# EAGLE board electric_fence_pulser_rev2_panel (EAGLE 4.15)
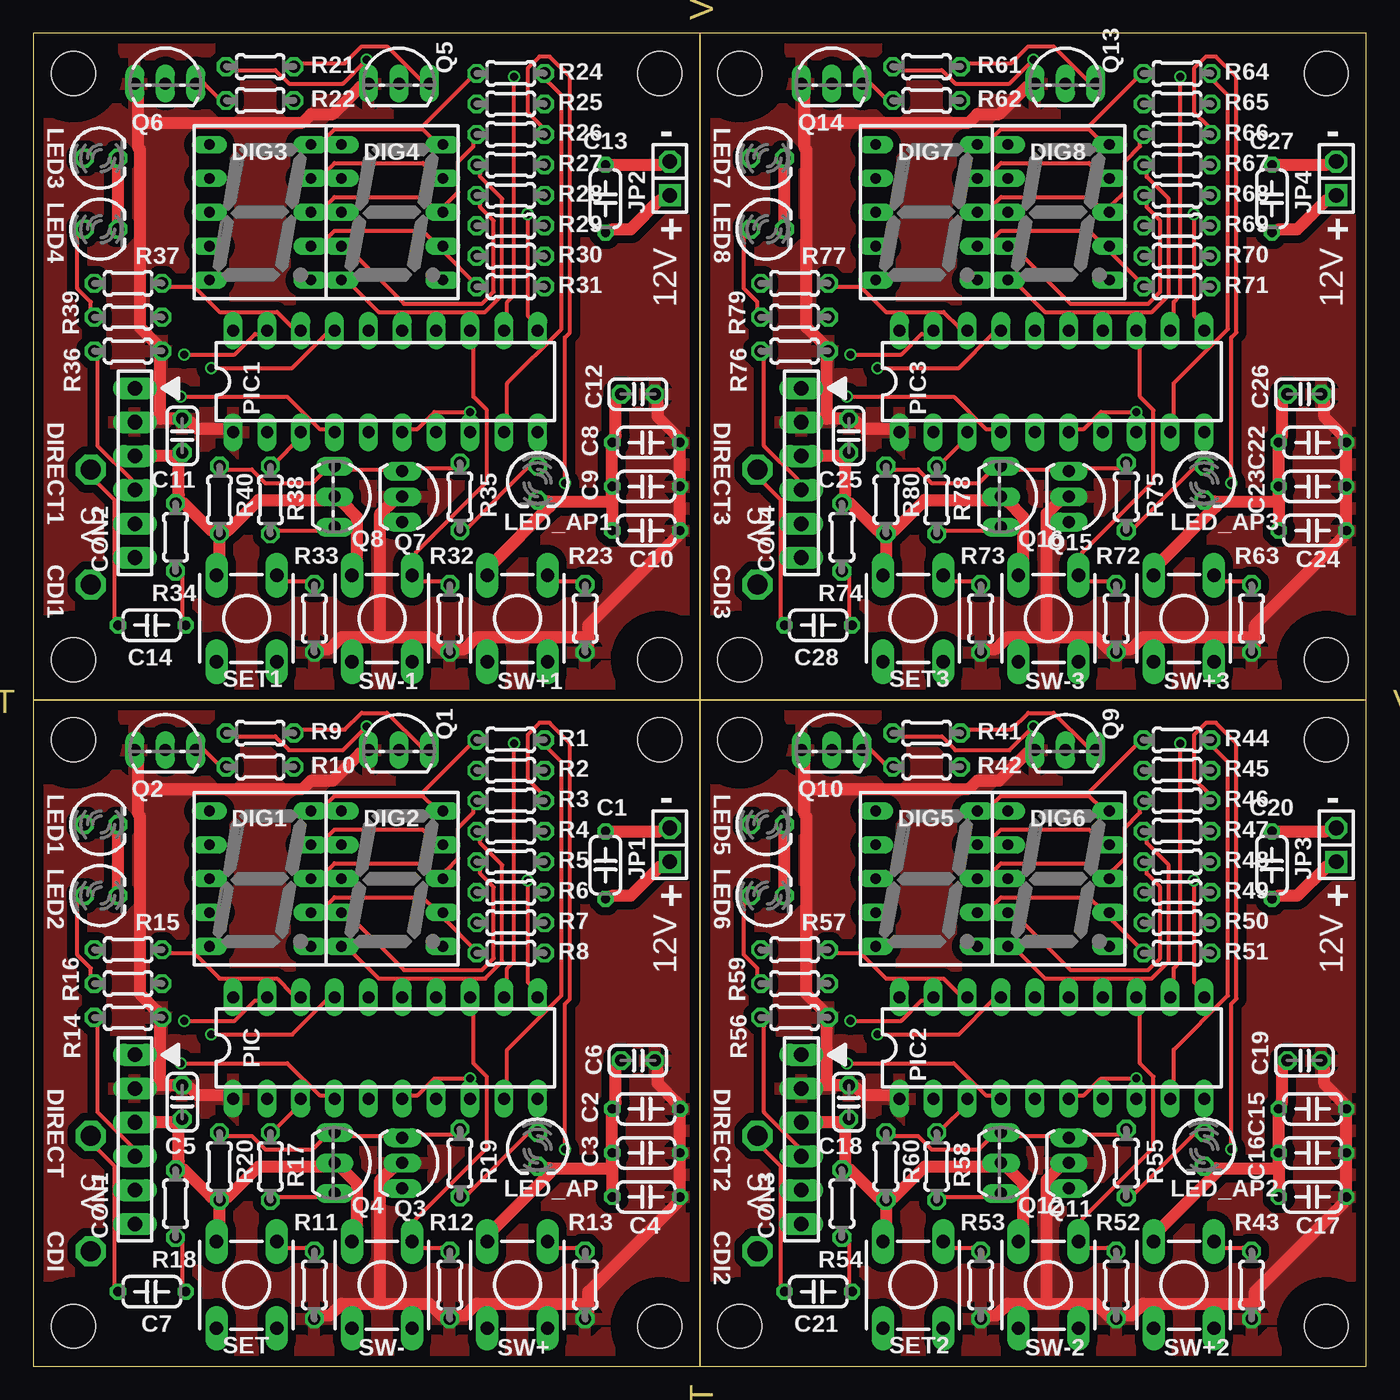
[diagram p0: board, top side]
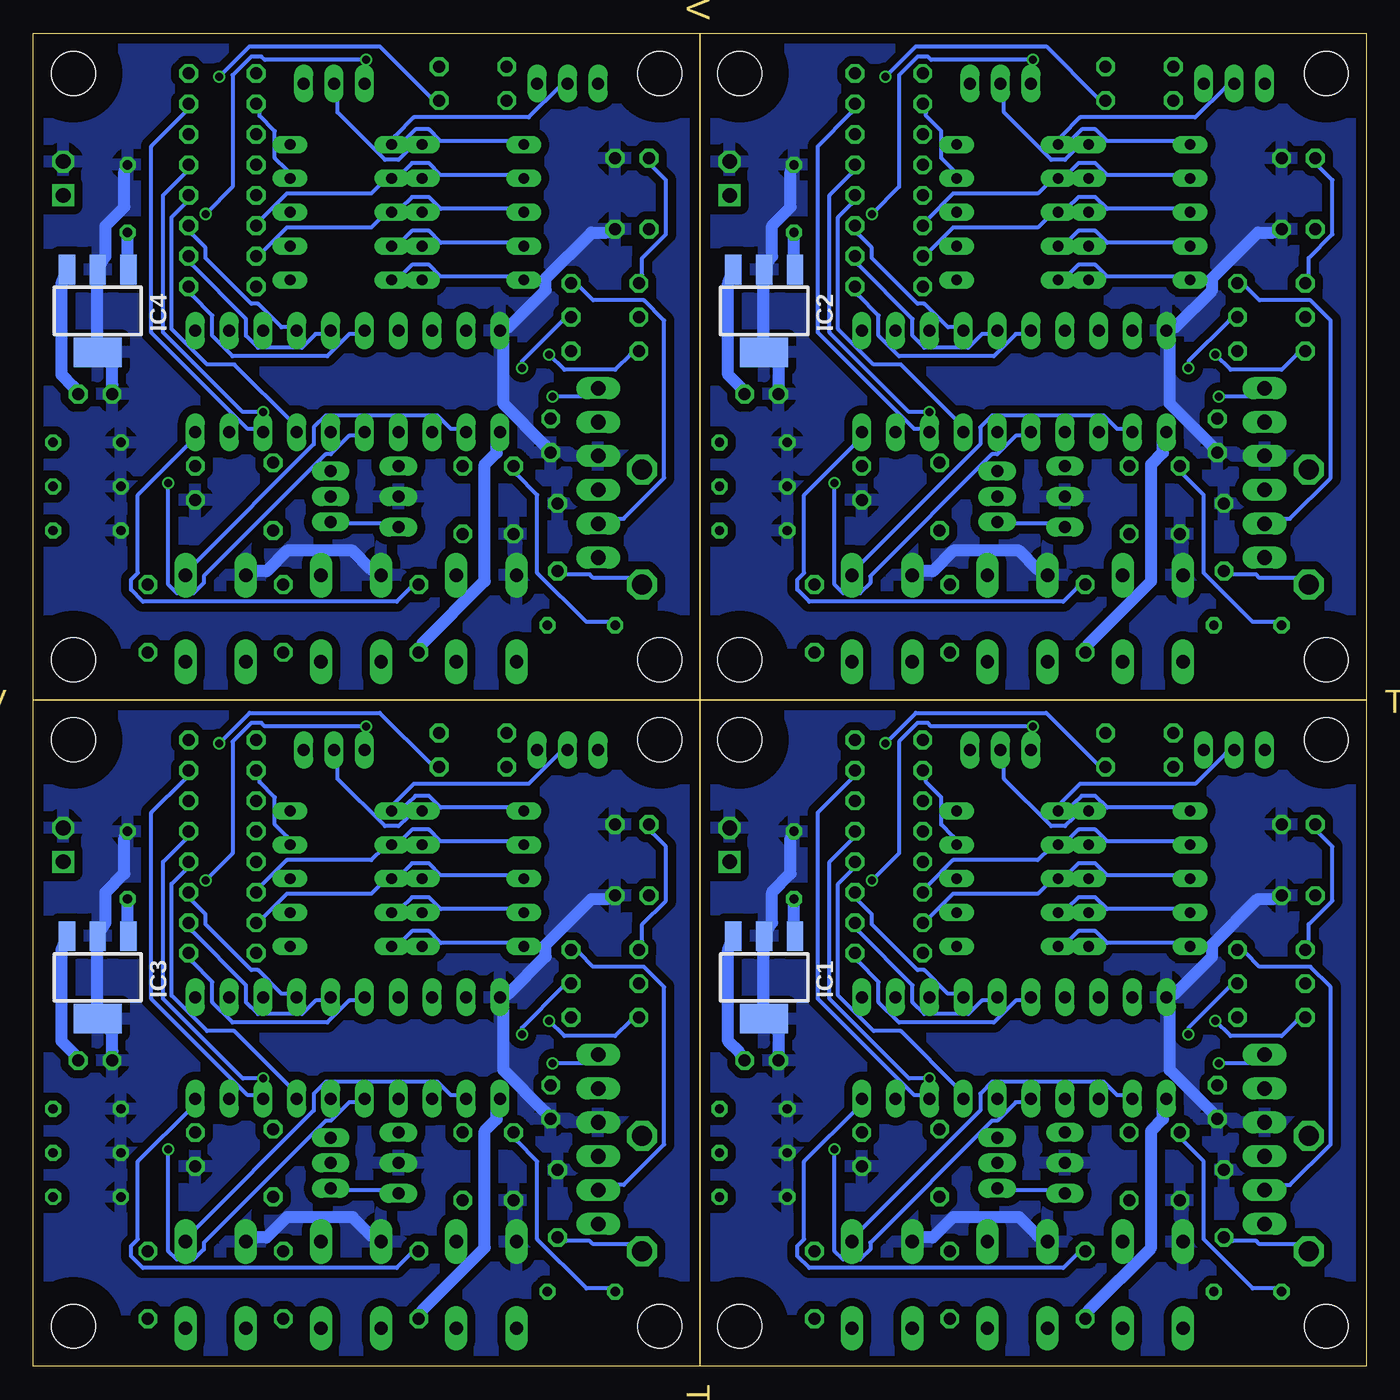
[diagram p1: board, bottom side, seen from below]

Size 100 x 100 mm. Coordinates in mm from the lower left corner, seen from the top.
Outline: 50,0 0,0 0,50
Outline: 50,0 50,50
Outline: 50,50 0,50
Outline: 0,50 50,50
Outline: 50,50 50,100
Outline: 50,100 0,100 0,50
Outline: 50,0 100,0 100,50
Outline: 100,50 50,50
Outline: 50,50 50,0
Outline: 50,50 100,50
Outline: 100,50 100,100 50,100
Outline: 50,100 50,50
Copper layers (1*16): Top 0.035mm / dielectric 1.5mm / Bottom 0.035mm
Design rules "FUSION_IIZUKA_STANDARD": minimum track width 6mil, minimum drill 0.6mm, track to track 8mil, track to pad 8mil, pad to pad 8mil, via to via 8mil, smd to smd 0mil, copper to edge 30mil, drill to drill 10mil, minimum pad ring 10mil, minimum via ring 6mil, stop-mask expansion 2mil, vias tented up to drill 100mil, thermal gap 24mil
Net classes: 0 default: width 0.305 mm, drill 0.305 mm; 1 POWER: width 0.889 mm, drill 0.457 mm
vRestrict: 3264 lines

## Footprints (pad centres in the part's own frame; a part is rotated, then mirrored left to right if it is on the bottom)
C050-024X044_OLMX = drill 0.7 octagon: 1 -2.54,0; 2 2.54,0
C025-024X044_OLMX = drill 0.9 octagon: 1 -1.27,0; 2 1.27,0
PAD_1.5 = drill 1.5 pad 2.184 octagon: P$1 0,0
PIC_ICSP = drill 1.1 long: MCLR -6.35,0; NC 6.35,0; PGC 3.81,0; PGD 1.27,0; VDD -3.81,0; VSS -1.27,0
HDSP-E_OLMX = drill 0.8 long: 1 -3.81,5.08; 2 -3.81,2.54; 3 -3.81,0; 4 -3.81,-2.54; 5 -3.81,-5.08; 6 3.81,-5.08; 7 3.81,-2.54; 8 3.81,0; 9 3.81,2.54; 10 3.81,5.08
3.0-HOLL-ONLY-RESTRICT = hole 3.3: 0,0
SOT223_OLMX = smd 1.219 x 2.235: 1 -2.311,-3.099; 2 0,-3.099; 3 2.311,-3.099 | smd 3.6 x 2.2: 4 0,3.099
1X02_OLMX = drill 1.1 square: 1 -1.27,0 | drill 1.1 octagon: 2 1.27,0
LED3MM_OLMX = drill 0.9 octagon: A -1.27,0; K 1.27,0
DIL20_OLMX = drill 0.9 long: 1 -11.43,-3.81; 2 -8.89,-3.81; 3 -6.35,-3.81; 4 -3.81,-3.81; 5 -1.27,-3.81; 6 1.27,-3.81; 7 3.81,-3.81; 8 6.35,-3.81; 9 8.89,-3.81; 10 11.43,-3.81; 11 11.43,3.81; 12 8.89,3.81; 13 6.35,3.81; 14 3.81,3.81; 15 1.27,3.81; 16 -1.27,3.81; 17 -3.81,3.81; 18 -6.35,3.81; 19 -8.89,3.81; 20 -11.43,3.81
TO-92-BCE?NALLOW = drill 0.9 long: B 2.286,0; C 0,0; E -2.286,0
TO92-BCE_OLMX_NALLOW = drill 0.9 long: B 1.905,0; C 0,0; E -1.905,0
0204/5_OLMX = drill 0.9 octagon: 1 -2.54,0; 2 2.54,0
TACT_SW = drill 1 pad 1.676 long: P$1_1 -2.261,3.251; P$1_2 2.261,3.251; P$2_1 -2.261,-3.251; P$2_2 2.261,-3.251

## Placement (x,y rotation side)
C1  10uF  [C050-024X044_OLMX]  42.93,37.59 270 top
C2  10uF  [C050-024X044_OLMX]  45.97,19.3 0 top
C3  10uF  [C050-024X044_OLMX]  45.97,16 0 top
C4  10uF  [C050-024X044_OLMX]  45.97,12.7 0 top
C5  0.1uF  [C025-024X044_OLMX]  11.18,19.81 90 top
C6  0.1uF  [C025-024X044_OLMX]  45.36,22.93 0 top
C7  0.1uF  [C050-024X044_OLMX]  8.89,5.59 180 top
C8  10uF  [C050-024X044_OLMX]  45.97,69.3 0 top
C9  10uF  [C050-024X044_OLMX]  45.97,66 0 top
C10  10uF  [C050-024X044_OLMX]  45.97,62.7 0 top
C11  0.1uF  [C025-024X044_OLMX]  11.18,69.81 90 top
C12  0.1uF  [C025-024X044_OLMX]  45.36,72.93 0 top
C13  10uF  [C050-024X044_OLMX]  42.93,87.59 270 top
C14  0.1uF  [C050-024X044_OLMX]  8.89,55.59 180 top
C15  10uF  [C050-024X044_OLMX]  95.97,19.3 0 top
C16  10uF  [C050-024X044_OLMX]  95.97,16 0 top
C17  10uF  [C050-024X044_OLMX]  95.97,12.7 0 top
C18  0.1uF  [C025-024X044_OLMX]  61.18,19.81 90 top
C19  0.1uF  [C025-024X044_OLMX]  95.36,22.93 0 top
C20  10uF  [C050-024X044_OLMX]  92.93,37.59 270 top
C21  0.1uF  [C050-024X044_OLMX]  58.89,5.59 180 top
C22  10uF  [C050-024X044_OLMX]  95.97,69.3 0 top
C23  10uF  [C050-024X044_OLMX]  95.97,66 0 top
C24  10uF  [C050-024X044_OLMX]  95.97,62.7 0 top
C25  0.1uF  [C025-024X044_OLMX]  61.18,69.81 90 top
C26  0.1uF  [C025-024X044_OLMX]  95.36,72.93 0 top
C27  10uF  [C050-024X044_OLMX]  92.93,87.59 270 top
C28  0.1uF  [C050-024X044_OLMX]  58.89,55.59 180 top
CDI  PAD1.5  [PAD_1.5]  4.32,8.64 270 top
CDI1  PAD1.5  [PAD_1.5]  4.32,58.64 270 top
CDI2  PAD1.5  [PAD_1.5]  54.32,8.64 270 top
CDI3  PAD1.5  [PAD_1.5]  54.32,58.64 270 top
CON1  ICSP  [PIC_ICSP]  7.62,17.02 270 top
CON2  ICSP  [PIC_ICSP]  7.62,67.02 270 top
CON3  ICSP  [PIC_ICSP]  57.62,17.02 270 top
CON4  ICSP  [PIC_ICSP]  57.62,67.02 270 top
DIG1  GL9A040G  [HDSP-E_OLMX]  17.02,36.58 0 top
DIG2  GL9A040G  [HDSP-E_OLMX]  26.92,36.58 0 top
DIG3  GL9A040G  [HDSP-E_OLMX]  17.02,86.58 0 top
DIG4  GL9A040G  [HDSP-E_OLMX]  26.92,86.58 0 top
DIG5  GL9A040G  [HDSP-E_OLMX]  67.02,36.58 0 top
DIG6  GL9A040G  [HDSP-E_OLMX]  76.92,36.58 0 top
DIG7  GL9A040G  [HDSP-E_OLMX]  67.02,86.58 0 top
DIG8  GL9A040G  [HDSP-E_OLMX]  76.92,86.58 0 top
DIRECT  PAD1.5  [PAD_1.5]  4.32,17.27 270 top
DIRECT1  PAD1.5  [PAD_1.5]  4.32,67.27 270 top
DIRECT2  PAD1.5  [PAD_1.5]  54.32,17.27 270 top
DIRECT3  PAD1.5  [PAD_1.5]  54.32,67.27 270 top
H1  MOUNT-HOLE  [3.0-HOLL-ONLY-RESTRICT]  47,47 0 top
H2  MOUNT-HOLE  [3.0-HOLL-ONLY-RESTRICT]  47,3 0 top
H3  MOUNT-HOLE  [3.0-HOLL-ONLY-RESTRICT]  3,3 0 top
H4  MOUNT-HOLE  [3.0-HOLL-ONLY-RESTRICT]  3,47 0 top
H5  MOUNT-HOLE  [3.0-HOLL-ONLY-RESTRICT]  47,97 0 top
H6  MOUNT-HOLE  [3.0-HOLL-ONLY-RESTRICT]  47,53 0 top
H7  MOUNT-HOLE  [3.0-HOLL-ONLY-RESTRICT]  3,53 0 top
H8  MOUNT-HOLE  [3.0-HOLL-ONLY-RESTRICT]  3,97 0 top
H9  MOUNT-HOLE  [3.0-HOLL-ONLY-RESTRICT]  97,47 0 top
H10  MOUNT-HOLE  [3.0-HOLL-ONLY-RESTRICT]  97,3 0 top
H11  MOUNT-HOLE  [3.0-HOLL-ONLY-RESTRICT]  53,3 0 top
H12  MOUNT-HOLE  [3.0-HOLL-ONLY-RESTRICT]  53,47 0 top
H13  MOUNT-HOLE  [3.0-HOLL-ONLY-RESTRICT]  97,97 0 top
H14  MOUNT-HOLE  [3.0-HOLL-ONLY-RESTRICT]  97,53 0 top
H15  MOUNT-HOLE  [3.0-HOLL-ONLY-RESTRICT]  53,53 0 top
H16  MOUNT-HOLE  [3.0-HOLL-ONLY-RESTRICT]  53,97 0 top
IC1  LM2940IMP  [SOT223_OLMX]  45.17,29.17 180 bottom
IC2  LM2940IMP  [SOT223_OLMX]  45.17,79.17 180 bottom
IC3  LM2940IMP  [SOT223_OLMX]  95.17,29.17 180 bottom
IC4  LM2940IMP  [SOT223_OLMX]  95.17,79.17 180 bottom
JP1  [1X02_OLMX]  47.75,39.12 90 top
JP2  [1X02_OLMX]  47.75,89.12 90 top
JP3  [1X02_OLMX]  97.75,39.12 90 top
JP4  [1X02_OLMX]  97.75,89.12 90 top
LED1  [LED3MM_OLMX]  5.08,40.64 0 top
LED2  [LED3MM_OLMX]  5.08,35.31 0 top
LED3  [LED3MM_OLMX]  5.08,90.64 0 top
LED4  [LED3MM_OLMX]  5.08,85.31 0 top
LED5  [LED3MM_OLMX]  55.08,40.64 0 top
LED6  [LED3MM_OLMX]  55.08,35.31 0 top
LED7  [LED3MM_OLMX]  55.08,90.64 0 top
LED8  [LED3MM_OLMX]  55.08,85.31 0 top
LED_AP  [LED3MM_OLMX]  37.85,16.26 270 top
LED_AP1  [LED3MM_OLMX]  37.85,66.26 270 top
LED_AP2  [LED3MM_OLMX]  87.85,16.26 270 top
LED_AP3  [LED3MM_OLMX]  87.85,66.26 270 top
PIC  PIC16F  [DIL20_OLMX]  26.42,23.88 0 top
PIC1  PIC16F  [DIL20_OLMX]  26.42,73.88 0 top
PIC2  PIC16F  [DIL20_OLMX]  76.42,23.88 0 top
PIC3  PIC16F  [DIL20_OLMX]  76.42,73.88 0 top
Q1  2SA1015Y  [TO-92-BCE?NALLOW]  27.43,46.23 0 top
Q2  2SA1015Y  [TO-92-BCE?NALLOW]  9.91,46.23 0 top
Q3  2SC1815Y  [TO92-BCE_OLMX_NALLOW]  27.69,15.24 270 top
Q4  2SA1015Y  [TO-92-BCE?NALLOW]  22.61,15.24 270 top
Q5  2SA1015Y  [TO-92-BCE?NALLOW]  27.43,96.23 0 top
Q6  2SA1015Y  [TO-92-BCE?NALLOW]  9.91,96.23 0 top
Q7  2SC1815Y  [TO92-BCE_OLMX_NALLOW]  27.69,65.24 270 top
Q8  2SA1015Y  [TO-92-BCE?NALLOW]  22.61,65.24 270 top
Q9  2SA1015Y  [TO-92-BCE?NALLOW]  77.43,46.23 0 top
Q10  2SA1015Y  [TO-92-BCE?NALLOW]  59.91,46.23 0 top
Q11  2SC1815Y  [TO92-BCE_OLMX_NALLOW]  77.69,15.24 270 top
Q12  2SA1015Y  [TO-92-BCE?NALLOW]  72.61,15.24 270 top
Q13  2SA1015Y  [TO-92-BCE?NALLOW]  77.43,96.23 0 top
Q14  2SA1015Y  [TO-92-BCE?NALLOW]  59.91,96.23 0 top
Q15  2SC1815Y  [TO92-BCE_OLMX_NALLOW]  77.69,65.24 270 top
Q16  2SA1015Y  [TO-92-BCE?NALLOW]  72.61,65.24 270 top
R1  220  [0204/5_OLMX]  35.81,46.99 0 top
R2  220  [0204/5_OLMX]  35.81,44.7 0 top
R3  220  [0204/5_OLMX]  35.81,42.42 0 top
R4  220  [0204/5_OLMX]  35.81,40.13 0 top
R5  220  [0204/5_OLMX]  35.81,37.85 0 top
R6  220  [0204/5_OLMX]  35.81,35.56 0 top
R7  220  [0204/5_OLMX]  35.81,33.27 0 top
R8  220  [0204/5_OLMX]  35.81,30.99 0 top
R9  4.7k  [0204/5_OLMX]  17.02,47.5 180 top
R10  4.7k  [0204/5_OLMX]  17.02,44.96 0 top
R11  10k  [0204/5_OLMX]  21.08,6.1 270 top
R12  10k  [0204/5_OLMX]  31.24,6.1 270 top
R13  10k  [0204/5_OLMX]  41.4,6.1 270 top
R14  10k  [0204/5_OLMX]  7.11,26.16 180 top
R15  1k  [0204/5_OLMX]  7.11,31.24 180 top
R16  1k  [0204/5_OLMX]  7.11,28.7 180 top
R17  1k  [0204/5_OLMX]  17.78,14.99 270 top
R18  10k  [0204/5_OLMX]  10.67,12.19 90 top
R19  1k  [0204/5_OLMX]  32,15.24 270 top
R20  1k  [0204/5_OLMX]  13.97,14.99 270 top
R21  4.7k  [0204/5_OLMX]  17.02,97.5 180 top
R22  4.7k  [0204/5_OLMX]  17.02,94.96 0 top
R23  10k  [0204/5_OLMX]  41.4,56.1 270 top
R24  220  [0204/5_OLMX]  35.81,96.99 0 top
R25  220  [0204/5_OLMX]  35.81,94.7 0 top
R26  220  [0204/5_OLMX]  35.81,92.42 0 top
R27  220  [0204/5_OLMX]  35.81,90.13 0 top
R28  220  [0204/5_OLMX]  35.81,87.85 0 top
R29  220  [0204/5_OLMX]  35.81,85.56 0 top
R30  220  [0204/5_OLMX]  35.81,83.27 0 top
R31  220  [0204/5_OLMX]  35.81,80.99 0 top
R32  10k  [0204/5_OLMX]  31.24,56.1 270 top
R33  10k  [0204/5_OLMX]  21.08,56.1 270 top
R34  10k  [0204/5_OLMX]  10.67,62.19 90 top
R35  1k  [0204/5_OLMX]  32,65.24 270 top
R36  10k  [0204/5_OLMX]  7.11,76.16 180 top
R37  1k  [0204/5_OLMX]  7.11,81.24 180 top
R38  1k  [0204/5_OLMX]  17.78,64.99 270 top
R39  1k  [0204/5_OLMX]  7.11,78.7 180 top
R40  1k  [0204/5_OLMX]  13.97,64.99 270 top
R41  4.7k  [0204/5_OLMX]  67.02,47.5 180 top
R42  4.7k  [0204/5_OLMX]  67.02,44.96 0 top
R43  10k  [0204/5_OLMX]  91.4,6.1 270 top
R44  220  [0204/5_OLMX]  85.81,46.99 0 top
R45  220  [0204/5_OLMX]  85.81,44.7 0 top
R46  220  [0204/5_OLMX]  85.81,42.42 0 top
R47  220  [0204/5_OLMX]  85.81,40.13 0 top
R48  220  [0204/5_OLMX]  85.81,37.85 0 top
R49  220  [0204/5_OLMX]  85.81,35.56 0 top
R50  220  [0204/5_OLMX]  85.81,33.27 0 top
R51  220  [0204/5_OLMX]  85.81,30.99 0 top
R52  10k  [0204/5_OLMX]  81.24,6.1 270 top
R53  10k  [0204/5_OLMX]  71.08,6.1 270 top
R54  10k  [0204/5_OLMX]  60.67,12.19 90 top
R55  1k  [0204/5_OLMX]  82,15.24 270 top
R56  10k  [0204/5_OLMX]  57.11,26.16 180 top
R57  1k  [0204/5_OLMX]  57.11,31.24 180 top
R58  1k  [0204/5_OLMX]  67.78,14.99 270 top
R59  1k  [0204/5_OLMX]  57.11,28.7 180 top
R60  1k  [0204/5_OLMX]  63.97,14.99 270 top
R61  4.7k  [0204/5_OLMX]  67.02,97.5 180 top
R62  4.7k  [0204/5_OLMX]  67.02,94.96 0 top
R63  10k  [0204/5_OLMX]  91.4,56.1 270 top
R64  220  [0204/5_OLMX]  85.81,96.99 0 top
R65  220  [0204/5_OLMX]  85.81,94.7 0 top
R66  220  [0204/5_OLMX]  85.81,92.42 0 top
R67  220  [0204/5_OLMX]  85.81,90.13 0 top
R68  220  [0204/5_OLMX]  85.81,87.85 0 top
R69  220  [0204/5_OLMX]  85.81,85.56 0 top
R70  220  [0204/5_OLMX]  85.81,83.27 0 top
R71  220  [0204/5_OLMX]  85.81,80.99 0 top
R72  10k  [0204/5_OLMX]  81.24,56.1 270 top
R73  10k  [0204/5_OLMX]  71.08,56.1 270 top
R74  10k  [0204/5_OLMX]  60.67,62.19 90 top
R75  1k  [0204/5_OLMX]  82,65.24 270 top
R76  10k  [0204/5_OLMX]  57.11,76.16 180 top
R77  1k  [0204/5_OLMX]  57.11,81.24 180 top
R78  1k  [0204/5_OLMX]  67.78,64.99 270 top
R79  1k  [0204/5_OLMX]  57.11,78.7 180 top
R80  1k  [0204/5_OLMX]  63.97,64.99 270 top
SET  PUSH_SWTACT  [TACT_SW]  16,6.1 0 top
SET1  PUSH_SWTACT  [TACT_SW]  16,56.1 0 top
SET2  PUSH_SWTACT  [TACT_SW]  66,6.1 0 top
SET3  PUSH_SWTACT  [TACT_SW]  66,56.1 0 top
SW+  PUSH_SWTACT  [TACT_SW]  36.32,6.1 0 top
SW+1  PUSH_SWTACT  [TACT_SW]  36.32,56.1 0 top
SW+2  PUSH_SWTACT  [TACT_SW]  86.32,6.1 0 top
SW+3  PUSH_SWTACT  [TACT_SW]  86.32,56.1 0 top
SW-  PUSH_SWTACT  [TACT_SW]  26.16,6.1 0 top
SW-1  PUSH_SWTACT  [TACT_SW]  26.16,56.1 0 top
SW-2  PUSH_SWTACT  [TACT_SW]  76.16,6.1 0 top
SW-3  PUSH_SWTACT  [TACT_SW]  76.16,56.1 0 top

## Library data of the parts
C1-C28 R1-R80 = rcl
CDI CDI1-CDI3 CON1-CON4 DIRECT DIRECT1-DIRECT3 SET SET1-SET3 SW+ SW+1-SW+3 SW- SW-1-SW-3 = 001mylib
DIG1-DIG8 = display-hp
H1-H16 = holes
IC1-IC4 = linear
JP1-JP4 = pinhead
LED1-LED8 LED_AP LED_AP1-LED_AP3 = led
PIC PIC1-PIC3 = microchip-5
Q1 Q2 Q4-Q6 Q8-Q10 Q12-Q14 Q16 = transistor-pnp
Q3 Q7 Q11 Q15 = transistor

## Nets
+12V [POWER]: C1.2 IC1.1 JP1.1
+12V1 [POWER]: C13.2 IC2.1 JP2.1
+12V2 [POWER]: C20.2 IC3.1 JP3.1
+12V3 [POWER]: C27.2 IC4.1 JP4.1
GND [POWER]: C1.1 C2.1 C3.1 C4.1 C5.1 C6.1 CON1.VSS IC1.2 IC1.4 JP1.2 LED1.K LED2.K LED_AP.K PIC.20 Q4.C R18.2 R20.2 SET.P$1_1 SW+.P$1_1 SW-.P$1_1
GND1 [POWER]: C8.1 C9.1 C10.1 C11.1 C12.1 C13.1 CON2.VSS IC2.2 IC2.4 JP2.2 LED3.K LED4.K LED_AP1.K PIC1.20 Q8.C R34.2 R40.2 SET1.P$1_1 SW+1.P$1_1 SW-1.P$1_1
GND2 [POWER]: C15.1 C16.1 C17.1 C18.1 C19.1 C20.1 CON3.VSS IC3.2 IC3.4 JP3.2 LED5.K LED6.K LED_AP2.K PIC2.20 Q12.C R54.2 R60.2 SET2.P$1_1 SW+2.P$1_1 SW-2.P$1_1
GND3 [POWER]: C22.1 C23.1 C24.1 C25.1 C26.1 C27.1 CON4.VSS IC4.2 IC4.4 JP4.2 LED7.K LED8.K LED_AP3.K PIC3.20 Q16.C R74.2 R80.2 SET3.P$1_1 SW+3.P$1_1 SW-3.P$1_1
N$1: DIG1.7 DIG2.7 R8.1
N$2: PIC.9 R1.2
N$3: PIC.12 R10.2
N$4: PIC.15 R7.2
N$5: PIC.14 R6.2
N$6: PIC.7 R5.2
N$7: PIC.6 R4.2
N$8: PIC.5 R3.2
N$9: PIC.13 R12.1 SW-.P$1_2
N$10: PIC.10 R11.1 SET.P$1_2
N$11: C7.1 CDI.P$1 R18.1
N$12: PIC.8 R2.2
N$13: LED_AP.A R19.2
N$14: CON1.MCLR PIC.4
N$15: DIG1.1 Q1.C
N$16: DIG2.1 Q2.C
N$17: PIC1.15 R30.2
N$18: PIC.11 R9.2
N$19: LED1.A R15.2
N$20: LED2.A R16.2
N$21: PIC1.14 R29.2
N$22: Q1.B R9.1
N$23: Q2.B R10.1
N$24: PIC.17 R16.1
N$25: Q3.B Q4.B R17.2
N$26: CON1.PGC PIC.18 R15.1
N$27: PIC.2 R13.1 SW+.P$1_2
N$28: PIC.3 R17.1
N$29: C7.2 DIRECT.P$1 Q3.E Q4.E R19.1 R20.1
N$30: PIC1.7 R28.2
N$31: DIG1.10 DIG2.10 R1.1
N$32: CON1.PGD PIC.19 R14.2
N$33: PIC1.6 R27.2
N$34: PIC1.5 R26.2
N$35: PIC.16 R8.2
N$36: PIC1.16 R31.2
N$37: DIG3.4 DIG4.4 R28.1
N$38: DIG3.10 DIG4.10 R24.1
N$39: DIG3.9 DIG4.9 R25.1
N$40: DIG3.5 DIG4.5 R27.1
N$41: DIG3.2 DIG4.2 R29.1
N$42: DIG1.9 DIG2.9 R2.1
N$43: DIG3.3 DIG4.3 R30.1
N$44: DIG1.5 DIG2.5 R4.1
N$45: DIG1.2 DIG2.2 R6.1
N$46: DIG1.4 DIG2.4 R5.1
N$47: DIG1.3 DIG2.3 R7.1
N$48: PIC1.12 R22.2
N$49: PIC1.11 R21.2
N$50: DIG3.8 DIG4.8 R26.1
N$51: DIG3.1 Q5.C
N$52: DIG4.1 Q6.C
N$53: Q5.B R21.1
N$54: Q6.B R22.1
N$55: DIG1.8 DIG2.8 R3.1
N$56: CON2.PGC PIC1.18 R37.1
N$57: PIC1.2 R23.1 SW+1.P$1_2
N$58: PIC1.3 R38.1
N$59: DIG3.7 DIG4.7 R31.1
N$60: PIC1.13 R32.1 SW-1.P$1_2
N$61: PIC1.10 R33.1 SET1.P$1_2
N$62: PIC1.9 R24.2
N$63: PIC1.8 R25.2
N$64: CON2.MCLR PIC1.4
N$65: C14.1 CDI1.P$1 R34.1
N$66: LED_AP1.A R35.2
N$67: PIC1.17 R39.1
N$68: CON2.PGD PIC1.19 R36.2
N$69: LED3.A R37.2
N$70: Q7.B Q8.B R38.2
N$71: C14.2 DIRECT1.P$1 Q7.E Q8.E R35.1 R40.1
N$72: LED4.A R39.2
N$73: PIC2.15 R50.2
N$74: PIC2.14 R49.2
N$75: PIC2.7 R48.2
N$76: PIC2.6 R47.2
N$77: PIC2.5 R46.2
N$78: PIC2.16 R51.2
N$79: DIG5.4 DIG6.4 R48.1
N$80: DIG5.10 DIG6.10 R44.1
N$81: DIG5.9 DIG6.9 R45.1
N$82: DIG5.5 DIG6.5 R47.1
N$83: DIG5.2 DIG6.2 R49.1
N$84: DIG5.3 DIG6.3 R50.1
N$85: PIC2.12 R42.2
N$86: PIC2.11 R41.2
N$87: DIG5.8 DIG6.8 R46.1
N$88: DIG5.1 Q9.C
N$89: DIG6.1 Q10.C
N$90: Q9.B R41.1
N$91: Q10.B R42.1
N$92: CON3.PGC PIC2.18 R57.1
N$93: PIC2.2 R43.1 SW+2.P$1_2
N$94: PIC2.3 R58.1
N$95: DIG5.7 DIG6.7 R51.1
N$96: PIC2.13 R52.1 SW-2.P$1_2
N$97: PIC2.10 R53.1 SET2.P$1_2
N$98: PIC2.9 R44.2
N$99: PIC2.8 R45.2
N$100: CON3.MCLR PIC2.4
N$101: C21.1 CDI2.P$1 R54.1
N$102: LED_AP2.A R55.2
N$103: PIC2.17 R59.1
N$104: CON3.PGD PIC2.19 R56.2
N$105: LED5.A R57.2
N$106: Q11.B Q12.B R58.2
N$107: C21.2 DIRECT2.P$1 Q11.E Q12.E R55.1 R60.1
N$108: LED6.A R59.2
N$109: PIC3.15 R70.2
N$110: PIC3.14 R69.2
N$111: PIC3.7 R68.2
N$112: PIC3.6 R67.2
N$113: PIC3.5 R66.2
N$114: PIC3.16 R71.2
N$115: DIG7.4 DIG8.4 R68.1
N$116: DIG7.10 DIG8.10 R64.1
N$117: DIG7.9 DIG8.9 R65.1
N$118: DIG7.5 DIG8.5 R67.1
N$119: DIG7.2 DIG8.2 R69.1
N$120: DIG7.3 DIG8.3 R70.1
N$121: PIC3.12 R62.2
N$122: PIC3.11 R61.2
N$123: DIG7.8 DIG8.8 R66.1
N$124: DIG7.1 Q13.C
N$125: DIG8.1 Q14.C
N$126: Q13.B R61.1
N$127: Q14.B R62.1
N$128: CON4.PGC PIC3.18 R77.1
N$129: PIC3.2 R63.1 SW+3.P$1_2
N$130: PIC3.3 R78.1
N$131: DIG7.7 DIG8.7 R71.1
N$132: PIC3.13 R72.1 SW-3.P$1_2
N$133: PIC3.10 R73.1 SET3.P$1_2
N$134: PIC3.9 R64.2
N$135: PIC3.8 R65.2
N$136: CON4.MCLR PIC3.4
N$137: C28.1 CDI3.P$1 R74.1
N$138: LED_AP3.A R75.2
N$139: PIC3.17 R79.1
N$140: CON4.PGD PIC3.19 R76.2
N$141: LED7.A R77.2
N$142: Q15.B Q16.B R78.2
N$143: C28.2 DIRECT3.P$1 Q15.E Q16.E R75.1 R80.1
N$144: LED8.A R79.2
VCC [POWER]: C2.2 C3.2 C4.2 C5.2 C6.2 CON1.VDD IC1.3 PIC.1 Q1.E Q2.E Q3.C R11.2 R12.2 R13.2 R14.1
VCC1 [POWER]: C8.2 C9.2 C10.2 C11.2 C12.2 CON2.VDD IC2.3 PIC1.1 Q5.E Q6.E Q7.C R23.2 R32.2 R33.2 R36.1
VCC2 [POWER]: C15.2 C16.2 C17.2 C18.2 C19.2 CON3.VDD IC3.3 PIC2.1 Q9.E Q10.E Q11.C R43.2 R52.2 R53.2 R56.1
VCC3 [POWER]: C22.2 C23.2 C24.2 C25.2 C26.2 CON4.VDD IC4.3 PIC3.1 Q13.E Q14.E Q15.C R63.2 R72.2 R73.2 R76.1

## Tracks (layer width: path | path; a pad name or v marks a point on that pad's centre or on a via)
+12V
  Top 0.889: C1.2 43.43,35.31 44.83,35.31 46.99,37.47 JP1.1
  Bottom 0.889: IC1.1 42.93,33.27 C1.2
+12V1
  Top 0.889: C13.2 43.43,85.31 44.83,85.31 46.99,87.47 JP2.1
  Bottom 0.889: IC2.1 42.93,83.27 C13.2
+12V2
  Top 0.889: C20.2 93.43,35.31 94.83,35.31 96.99,37.47 JP3.1
  Bottom 0.889: IC3.1 92.93,33.27 C20.2
+12V3
  Top 0.889: C27.2 93.43,85.31 94.83,85.31 96.99,87.47 JP4.1
  Bottom 0.889: IC4.1 92.93,83.27 C27.2
GND
  Top 0.889: 43.43,14.86 C4.1 | 43.43,14.86 C3.1 C2.1 43.69,19.81 43.69,22.35 C6.1 | 38.73,14.86 38.48,14.86 LED_AP.K | 38.73,14.86 43.43,14.86 | SW+.P$1_1 34.42,10.16 38.73,14.48 38.73,14.86 | C1.1 46.99,40.13 JP1.2 | SW-.P$1_1 24.26,10.16 24.26,13.72 23.11,14.86 Q4.C 21.97,14.99 16.89,14.99 14.61,12.7 R20.2 | LED2.K LED1.K | R20.2 13.97,10.16 SET.P$1_1 | CON1.VSS 10.54,18.29 C5.1 10.92,17.91 10.92,15.37 R18.2 11.3,14.73 13.34,12.7 R20.2
  Bottom 0.889: C6.1 44.07,23.62 44.07,25.02 IC1.4 45.21,27.05 45.21,31.24 IC1.2 44.58,33.27 44.58,35.56 43.18,36.96 43.18,39.62 C1.1 | C5.1 11.56,19.05 14.73,22.23 14.73,27.05 PIC.20 14.35,27.94 11.56,30.73 11.56,31.62 8.13,35.05 6.99,35.05 LED2.K | SW+.P$1_1 33.27,9.65 32.51,9.65 30.99,11.18 26.04,11.18 24.64,9.78 SW-.P$1_1
  pour Bottom (isolate 0.61): 0,50 50,50 50,0 0,0
GND1
  Top 0.889: 43.43,64.86 C10.1 | 43.43,64.86 C9.1 C8.1 43.69,69.81 43.69,72.35 C12.1 | 38.73,64.86 38.48,64.86 LED_AP1.K | 38.73,64.86 43.43,64.86 | SW+1.P$1_1 34.42,60.16 38.73,64.48 38.73,64.86 | C13.1 46.99,90.13 JP2.2 | SW-1.P$1_1 24.26,60.16 24.26,63.72 23.11,64.86 Q8.C 21.97,64.99 16.89,64.99 14.61,62.7 R40.2 | LED4.K LED3.K | R40.2 13.97,60.16 SET1.P$1_1 | CON2.VSS 10.54,68.29 C11.1 10.92,67.91 10.92,65.37 R34.2 11.3,64.73 13.34,62.7 R40.2
  Bottom 0.889: C12.1 44.07,73.62 44.07,75.02 IC2.4 45.21,77.05 45.21,81.24 IC2.2 44.58,83.27 44.58,85.56 43.18,86.96 43.18,89.62 C13.1 | C11.1 11.56,69.05 14.73,72.22 14.73,77.05 PIC1.20 14.35,77.94 11.56,80.73 11.56,81.62 8.13,85.05 6.99,85.05 LED4.K | SW+1.P$1_1 33.27,59.65 32.51,59.65 30.99,61.18 26.04,61.18 24.64,59.78 SW-1.P$1_1
  pour Bottom (isolate 0.61): 0,100 50,100 50,50 0,50
GND2
  Top 0.889: 93.43,14.86 C17.1 | 93.43,14.86 C16.1 C15.1 93.69,19.81 93.69,22.35 C19.1 | 88.73,14.86 88.48,14.86 LED_AP2.K | 88.73,14.86 93.43,14.86 | SW+2.P$1_1 84.42,10.16 88.73,14.48 88.73,14.86 | C20.1 96.99,40.13 JP3.2 | SW-2.P$1_1 74.26,10.16 74.26,13.72 73.11,14.86 Q12.C 71.97,14.99 66.89,14.99 64.61,12.7 R60.2 | LED6.K LED5.K | R60.2 63.97,10.16 SET2.P$1_1 | CON3.VSS 60.54,18.29 C18.1 60.92,17.91 60.92,15.37 R54.2 61.3,14.73 63.34,12.7 R60.2
  Bottom 0.889: C19.1 94.07,23.62 94.07,25.02 IC3.4 95.21,27.05 95.21,31.24 IC3.2 94.58,33.27 94.58,35.56 93.18,36.96 93.18,39.62 C20.1 | C18.1 61.56,19.05 64.73,22.23 64.73,27.05 PIC2.20 64.35,27.94 61.56,30.73 61.56,31.62 58.13,35.05 56.98,35.05 LED6.K | SW+2.P$1_1 83.27,9.65 82.51,9.65 80.99,11.18 76.03,11.18 74.64,9.78 SW-2.P$1_1
  pour Bottom (isolate 0.61): 50,50 100,50 100,0 50,0
GND3
  Top 0.889: 93.43,64.86 C24.1 | 93.43,64.86 C23.1 C22.1 93.69,69.81 93.69,72.35 C26.1 | 88.73,64.86 88.48,64.86 LED_AP3.K | 88.73,64.86 93.43,64.86 | SW+3.P$1_1 84.42,60.16 88.73,64.48 88.73,64.86 | C27.1 96.99,90.13 JP4.2 | SW-3.P$1_1 74.26,60.16 74.26,63.72 73.11,64.86 Q16.C 71.97,64.99 66.89,64.99 64.61,62.7 R80.2 | LED8.K LED7.K | R80.2 63.97,60.16 SET3.P$1_1 | CON4.VSS 60.54,68.29 C25.1 60.92,67.91 60.92,65.37 R74.2 61.3,64.73 63.34,62.7 R80.2
  Bottom 0.889: C26.1 94.07,73.62 94.07,75.02 IC4.4 95.21,77.05 95.21,81.24 IC4.2 94.58,83.27 94.58,85.56 93.18,86.96 93.18,89.62 C27.1 | C25.1 61.56,69.05 64.73,72.22 64.73,77.05 PIC3.20 64.35,77.94 61.56,80.73 61.56,81.62 58.13,85.05 56.98,85.05 LED8.K | SW+3.P$1_1 83.27,59.65 82.51,59.65 80.99,61.18 76.03,61.18 74.64,59.78 SW-3.P$1_1
  pour Bottom (isolate 0.61): 50,100 100,100 100,50 50,50
N$1
  Top 0.305: DIG1.7 21.46,34.29 21.72,34.29 22.61,35.18 29.21,35.18 30.1,34.29 DIG2.7 30.99,33.4 32.89,31.5 R8.1
N$2
  Top 0.305: PIC.9 35.56,20.7 35.56,23.75 39.62,27.81 39.62,45.34 38.61,46.35 R1.2
N$3  (via drill 0.6)
  Top 0.305: v36.07,46.74 36.07,30.35 35.56,29.84 35.56,28.32 PIC.12
  Bottom 0.305: v36.07,46.74 33.78,49.02 24,49.02 20.19,45.21 R10.2
N$4
  Bottom 0.305: PIC.15 28.32,27.43 28.83,27.43 29.84,26.42 33.15,26.42 34.04,27.3 34.04,28.57 38.1,32.64 R7.2
N$5
  Bottom 0.305: PIC.14 30.86,27.94 31.37,27.94 33.15,29.72 33.66,29.72 37.08,33.15 37.08,33.91 38.1,34.92 R6.2
N$6
  Bottom 0.305: PIC.7 30.48,20.7 34.92,25.15 36.96,25.15 39.62,27.81 39.62,36.2 38.61,37.21 R5.2
N$7  (via drill 0.6)
  Top 0.305: v32.77,21.59 30.1,21.59 28.83,20.32 28.32,20.32 PIC.6
  Bottom 0.305: v32.77,21.59 34.29,21.59 40.26,27.56 40.26,37.85 38.61,39.5 R4.2
N$8  (via drill 0.6)
  Top 0.305: v39.88,16.26 39.88,27.18 40.26,27.56 40.26,46.74 38.73,48.26 37.97,48.26 37.08,47.37 37.08,44.07 38.1,43.05 R3.2
  Bottom 0.305: v39.88,16.26 39.88,8.64 39.24,8 37.97,8 37.21,8.76 37.21,9.27 28.07,18.41 27.69,18.41 26.29,19.81 25.78,19.81 PIC.5
N$9
  Top 0.305: R12.1 30.61,8.89 29.08,8.89 SW-.P$1_2 28.7,10.16 28.7,11.05 34.04,16.38 34.04,21.72 33.02,22.73 33.02,27.05 PIC.13
N$10
  Top 0.305: R11.1 20.45,8.89 18.92,8.89 SET.P$1_2
  Bottom 0.305: PIC.10 38.1,19.43 42.16,15.37 42.16,9.53 42.67,9.02 42.67,8.26 41.78,7.37 22.73,7.37 21.72,8.38 R11.1
N$11
  Top 0.305: C7.1 11.18,6.1 11.18,9.27 R18.1
  Bottom 0.305: R18.1 10.03,9.4 8.26,9.4 8,9.14 5.33,9.14 CDI.P$1
N$12
  Bottom 0.305: PIC.8 33.4,20.32 33.91,20.32 41.15,27.56 41.15,41.53 38.61,44.07 R2.2
N$13
  Top 0.305: R19.2 32.64,12.95 37.21,17.53 LED_AP.A
N$14  (via drill 0.6)
  Top 0.305: v11.05,22.73 19.05,22.73 21.46,20.32 21.97,20.32 PIC.4
  Bottom 0.305: v11.05,22.73 8.13,22.73 CON1.MCLR
N$15
  Bottom 0.305: DIG1.1 13.84,41.91 19.43,41.91 20.32,42.8 21.34,42.8 21.97,42.16 21.97,41.15 22.61,40.51 23.62,40.51 27.18,44.07 27.18,45.59 Q1.C
N$16
  Bottom 0.305: DIG2.1 22.86,42.29 21.46,43.69 12.83,43.69 10.54,45.97 Q2.C
N$17
  Bottom 0.305: PIC1.15 28.32,77.43 28.83,77.43 29.84,76.42 33.15,76.42 34.04,77.31 34.04,78.58 38.1,82.64 R30.2
N$18  (via drill 0.6)
  Top 0.305: v25.02,48.01 23.24,46.23 19.18,46.23 18.16,47.24 15.11,47.24 R9.2 | v37.08,36.45 37.08,28.83 37.59,28.32 PIC.11
  Bottom 0.305: v25.02,48.01 32.64,48.01 32.89,48.26 33.66,48.26 35.05,46.86 35.05,38.48 v37.08,36.45
N$19
  Bottom 0.305: R15.2 4.32,31.88 4.32,33.15 2.54,34.92 2.54,38.99 3.56,40.01 LED1.A
N$20
  Top 0.305: R16.2 4.32,29.34 4.32,29.84 3.3,30.86 3.3,34.92 LED2.A
N$21
  Bottom 0.305: PIC1.14 30.86,77.94 31.37,77.94 33.15,79.72 33.66,79.72 37.08,83.15 37.08,83.91 38.1,84.92 R29.2
N$22
  Top 0.305: R9.1 20.19,47.75 23.37,47.75 24.64,49.02 26.54,49.02 29.08,46.48 Q1.B
N$23
  Top 0.305: R10.1 13.84,45.21 12.83,46.23 Q2.B
N$24  (via drill 0.6)
  Top 0.305: v13.34,24.89 19.43,24.89 21.97,27.43 PIC.17
  Bottom 0.305: v13.34,24.89 13.34,25.4 10.29,28.45 R16.1
N$25
  Top 0.305: R17.2 18.41,12.7 21.97,12.7 Q4.B
  Bottom 0.305: Q3.B 27.05,13.21 23.24,13.21 Q4.B
N$26
  Top 0.305: R15.1 10.29,30.99 12.06,30.99 13.97,29.08 18.29,29.08 19.43,27.94 PIC.18
  Bottom 0.305: CON1.PGC 6.86,13.59 5.71,13.59 2.67,16.64 2.67,28.45 4.19,29.97 8,29.97 9.02,30.99 R15.1
N$27
  Top 0.305: R13.1 40.77,8.89 39.24,8.89 SW+.P$1_2
  Bottom 0.305: PIC.2 18.16,20.32 18.67,20.32 19.68,21.34 28.07,21.34 28.96,20.45 28.96,19.18 38.1,10.03 SW+.P$1_2
N$28
  Top 0.305: R17.1 18.29,17.91 19.81,19.43 PIC.3
N$29
  Top 0.305: C7.2 6.1,6.1 6.1,14.99 4.83,16.26 DIRECT.P$1 | R19.1 31.5,17.4 28.32,17.4 Q3.E 27.05,17.27 23.24,17.27 Q4.E 21.97,17.27 20.95,16.26 17.4,16.26 16.38,17.27 14.61,17.27 R20.1
  Bottom 0.305: C7.2 6.86,5.84 8.51,5.84 12.19,9.53 12.19,15.37 13.72,16.89 R20.1
N$30
  Bottom 0.305: PIC1.7 30.48,70.7 34.92,75.15 36.96,75.15 39.62,77.81 39.62,86.19 38.61,87.21 R28.2
N$31
  Top 0.305: 29.08,42.8 29.21,42.8 30.1,41.91 DIG2.10 | 29.08,42.8 22.61,42.8 21.72,41.91 21.46,41.91 DIG1.10 | R1.1 32.77,46.61 29.08,42.93 29.08,42.8
N$32  (via drill 0.6)
  Top 0.305: R14.2 4.83,25.53 4.83,19.05 7.37,16.51 CON1.PGD | v11.3,25.91 15.11,25.91 16.64,27.43 16.89,27.43 PIC.19
  Bottom 0.305: v11.3,25.91 10.16,24.77 6.35,24.77 5.21,25.91 R14.2
N$33  (via drill 0.6)
  Top 0.305: v32.77,71.59 30.1,71.59 28.83,70.32 28.32,70.32 PIC1.6
  Bottom 0.305: v32.77,71.59 34.29,71.59 40.26,77.56 40.26,87.85 38.61,89.5 R27.2
N$34  (via drill 0.6)
  Top 0.305: v39.88,66.26 39.88,77.18 40.26,77.56 40.26,96.74 38.73,98.26 37.97,98.26 37.08,97.37 37.08,94.07 38.1,93.05 R26.2
  Bottom 0.305: v39.88,66.26 39.88,58.64 39.24,58 37.97,58 37.21,58.76 37.21,59.27 28.07,68.42 27.69,68.42 26.29,69.81 25.78,69.81 PIC1.5
N$35
  Bottom 0.305: PIC.16 25.78,27.43 26.29,27.43 27.94,25.78 35.05,25.78 36.58,27.3 36.58,28.83 38.1,30.35 R8.2
N$36
  Bottom 0.305: PIC1.16 25.78,77.43 26.29,77.43 27.94,75.78 35.05,75.78 36.58,77.31 36.58,78.83 38.1,80.35 R31.2
N$37
  Top 0.305: R28.1 33.53,87.21 33.53,86.96 34.54,85.94 34.54,80.61 33.66,79.72 27.81,79.72 23.75,83.78 DIG4.4
  Bottom 0.305: DIG3.4 13.84,84.29 19.43,84.29 20.32,85.18 21.59,85.18 22.48,84.29 DIG4.4
N$38
  Top 0.305: 29.08,92.8 29.21,92.8 30.1,91.91 DIG4.10 | 29.08,92.8 22.61,92.8 21.72,91.91 21.46,91.91 DIG3.10 | R24.1 32.77,96.61 29.08,92.93 29.08,92.8
N$39
  Top 0.305: DIG3.9 21.46,89.37 21.72,89.37 22.61,90.26 29.21,90.26 30.1,89.37 DIG4.9
  Bottom 0.305: R25.1 33.02,94.07 33.02,93.81 31.88,92.67 31.88,90.64 30.99,89.75 DIG4.9
N$40
  Top 0.305: R27.1 33.53,89.5 33.53,89.24 35.18,87.59 35.18,80.35 33.91,79.08 25.91,79.08 23.75,81.24 DIG4.5
  Bottom 0.305: DIG3.5 13.84,81.75 19.43,81.75 20.32,82.64 21.59,82.64 22.48,81.75 DIG4.5
N$41
  Bottom 0.305: DIG3.2 13.84,89.37 19.43,89.37 20.32,90.26 21.59,90.26 22.48,89.37 DIG4.2 23.75,88.86 24.64,87.97 30.99,87.97 32.89,86.07 R29.1
N$42
  Top 0.305: DIG1.9 21.46,39.37 21.72,39.37 22.61,40.26 29.21,40.26 30.1,39.37 DIG2.9
  Bottom 0.305: R2.1 33.02,44.07 33.02,43.81 31.88,42.67 31.88,40.64 30.99,39.75 DIG2.9
N$43
  Bottom 0.305: DIG3.3 13.84,86.83 19.43,86.83 20.32,87.72 21.59,87.72 22.48,86.83 DIG4.3 23.75,86.32 24.64,85.43 30.99,85.43 32.77,83.66 R30.1
N$44
  Top 0.305: R4.1 33.53,39.5 33.53,39.24 35.18,37.59 35.18,30.35 33.91,29.08 25.91,29.08 23.75,31.24 DIG2.5
  Bottom 0.305: DIG1.5 13.84,31.75 19.43,31.75 20.32,32.64 21.59,32.64 22.48,31.75 DIG2.5
N$45
  Bottom 0.305: DIG1.2 13.84,39.37 19.43,39.37 20.32,40.26 21.59,40.26 22.48,39.37 DIG2.2 23.75,38.86 24.64,37.97 30.99,37.97 32.89,36.07 R6.1
N$46
  Top 0.305: R5.1 33.53,37.21 33.53,36.96 34.54,35.94 34.54,30.61 33.66,29.72 27.81,29.72 23.75,33.78 DIG2.4
  Bottom 0.305: DIG1.4 13.84,34.29 19.43,34.29 20.32,35.18 21.59,35.18 22.48,34.29 DIG2.4
N$47
  Bottom 0.305: DIG1.3 13.84,36.83 19.43,36.83 20.32,37.72 21.59,37.72 22.48,36.83 DIG2.3 23.75,36.32 24.64,35.43 30.99,35.43 32.77,33.66 R7.1
N$48  (via drill 0.6)
  Top 0.305: v36.07,96.74 36.07,80.35 35.56,79.84 35.56,78.32 PIC1.12
  Bottom 0.305: v36.07,96.74 33.78,99.02 24,99.02 20.19,95.21 R22.2
N$49  (via drill 0.6)
  Top 0.305: v25.02,98.01 23.24,96.23 19.18,96.23 18.16,97.24 15.11,97.24 R21.2 | v37.08,86.45 37.08,78.83 37.59,78.32 PIC1.11
  Bottom 0.305: v25.02,98.01 32.64,98.01 32.89,98.26 33.66,98.26 35.05,96.86 35.05,88.48 v37.08,86.45
N$50
  Top 0.305: DIG3.8 21.46,86.83 21.72,86.83 22.61,87.72 29.21,87.72 30.1,86.83 DIG4.8 30.99,87.21 31.88,88.1 31.88,90.39 33.02,91.53 33.02,91.78 R26.1
N$51
  Bottom 0.305: DIG3.1 13.84,91.91 19.43,91.91 20.32,92.8 21.34,92.8 21.97,92.16 21.97,91.15 22.61,90.51 23.62,90.51 27.18,94.07 27.18,95.59 Q5.C
N$52
  Bottom 0.305: DIG4.1 22.86,92.29 21.46,93.69 12.83,93.69 10.54,95.97 Q6.C
N$53
  Top 0.305: R21.1 20.19,97.75 23.37,97.75 24.64,99.02 26.54,99.02 29.08,96.48 Q5.B
N$54
  Top 0.305: R22.1 13.84,95.21 12.83,96.23 Q6.B
N$55
  Top 0.305: DIG1.8 21.46,36.83 21.72,36.83 22.61,37.72 29.21,37.72 30.1,36.83 DIG2.8 30.99,37.21 31.88,38.1 31.88,40.39 33.02,41.53 33.02,41.78 R3.1
N$56
  Top 0.305: R37.1 10.29,80.99 12.06,80.99 13.97,79.08 18.29,79.08 19.43,77.94 PIC1.18
  Bottom 0.305: CON2.PGC 6.86,63.59 5.71,63.59 2.67,66.64 2.67,78.45 4.19,79.97 8,79.97 9.02,80.99 R37.1
N$57
  Top 0.305: R23.1 40.77,58.89 39.24,58.89 SW+1.P$1_2
  Bottom 0.305: PIC1.2 18.16,70.32 18.67,70.32 19.68,71.34 28.07,71.34 28.96,70.45 28.96,69.18 38.1,60.03 SW+1.P$1_2
N$58
  Top 0.305: R38.1 18.29,67.91 19.81,69.43 PIC1.3
N$59
  Top 0.305: DIG3.7 21.46,84.29 21.72,84.29 22.61,85.18 29.21,85.18 30.1,84.29 DIG4.7 30.99,83.4 32.89,81.5 R31.1
N$60
  Top 0.305: R32.1 30.61,58.89 29.08,58.89 SW-1.P$1_2 28.7,60.16 28.7,61.05 34.04,66.38 34.04,71.72 33.02,72.73 33.02,77.05 PIC1.13
N$61
  Top 0.305: R33.1 20.45,58.89 18.92,58.89 SET1.P$1_2
  Bottom 0.305: PIC1.10 38.1,69.43 42.16,65.37 42.16,59.52 42.67,59.02 42.67,58.26 41.78,57.37 22.73,57.37 21.72,58.38 R33.1
N$62
  Top 0.305: PIC1.9 35.56,70.7 35.56,73.75 39.62,77.81 39.62,95.34 38.61,96.36 R24.2
N$63
  Bottom 0.305: PIC1.8 33.4,70.32 33.91,70.32 41.15,77.56 41.15,91.53 38.61,94.07 R25.2
N$64  (via drill 0.6)
  Top 0.305: v11.05,72.73 19.05,72.73 21.46,70.32 21.97,70.32 PIC1.4
  Bottom 0.305: v11.05,72.73 8.13,72.73 CON2.MCLR
N$65
  Top 0.305: C14.1 11.18,56.1 11.18,59.27 R34.1
  Bottom 0.305: R34.1 10.03,59.4 8.26,59.4 8,59.14 5.33,59.14 CDI1.P$1
N$66
  Top 0.305: R35.2 32.64,62.95 37.21,67.53 LED_AP1.A
N$67  (via drill 0.6)
  Top 0.305: v13.34,74.89 19.43,74.89 21.97,77.43 PIC1.17
  Bottom 0.305: v13.34,74.89 13.34,75.4 10.29,78.45 R39.1
N$68  (via drill 0.6)
  Top 0.305: R36.2 4.83,75.53 4.83,69.05 7.37,66.51 CON2.PGD | v11.3,75.91 15.11,75.91 16.64,77.43 16.89,77.43 PIC1.19
  Bottom 0.305: v11.3,75.91 10.16,74.77 6.35,74.77 5.21,75.91 R36.2
N$69
  Bottom 0.305: R37.2 4.32,81.88 4.32,83.15 2.54,84.92 2.54,88.99 3.56,90 LED3.A
N$70
  Top 0.305: R38.2 18.41,62.7 21.97,62.7 Q8.B
  Bottom 0.305: Q7.B 27.05,63.21 23.24,63.21 Q8.B
N$71
  Top 0.305: C14.2 6.1,56.1 6.1,64.99 4.83,66.26 DIRECT1.P$1 | R35.1 31.5,67.4 28.32,67.4 Q7.E 27.05,67.27 23.24,67.27 Q8.E 21.97,67.27 20.95,66.26 17.4,66.26 16.38,67.27 14.61,67.27 R40.1
  Bottom 0.305: C14.2 6.86,55.84 8.51,55.84 12.19,59.52 12.19,65.37 13.72,66.89 R40.1
N$72
  Top 0.305: R39.2 4.32,79.34 4.32,79.84 3.3,80.86 3.3,84.92 LED4.A
N$73
  Bottom 0.305: PIC2.15 78.32,27.43 78.83,27.43 79.84,26.42 83.15,26.42 84.04,27.3 84.04,28.57 88.1,32.64 R50.2
N$74
  Bottom 0.305: PIC2.14 80.86,27.94 81.37,27.94 83.15,29.72 83.66,29.72 87.08,33.15 87.08,33.91 88.1,34.92 R49.2
N$75
  Bottom 0.305: PIC2.7 80.48,20.7 84.92,25.15 86.96,25.15 89.62,27.81 89.62,36.2 88.61,37.21 R48.2
N$76  (via drill 0.6)
  Top 0.305: v82.77,21.59 80.1,21.59 78.83,20.32 78.32,20.32 PIC2.6
  Bottom 0.305: v82.77,21.59 84.29,21.59 90.26,27.56 90.26,37.85 88.61,39.5 R47.2
N$77  (via drill 0.6)
  Top 0.305: v89.88,16.26 89.88,27.18 90.26,27.56 90.26,46.74 88.73,48.26 87.97,48.26 87.08,47.37 87.08,44.07 88.1,43.05 R46.2
  Bottom 0.305: v89.88,16.26 89.88,8.64 89.24,8 87.97,8 87.21,8.76 87.21,9.27 78.07,18.41 77.69,18.41 76.29,19.81 75.78,19.81 PIC2.5
N$78
  Bottom 0.305: PIC2.16 75.78,27.43 76.29,27.43 77.94,25.78 85.05,25.78 86.58,27.3 86.58,28.83 88.1,30.35 R51.2
N$79
  Top 0.305: R48.1 83.53,37.21 83.53,36.96 84.54,35.94 84.54,30.61 83.66,29.72 77.81,29.72 73.75,33.78 DIG6.4
  Bottom 0.305: DIG5.4 63.84,34.29 69.43,34.29 70.32,35.18 71.59,35.18 72.48,34.29 DIG6.4
N$80
  Top 0.305: 79.08,42.8 79.21,42.8 80.1,41.91 DIG6.10 | 79.08,42.8 72.61,42.8 71.72,41.91 71.46,41.91 DIG5.10 | R44.1 82.77,46.61 79.08,42.93 79.08,42.8
N$81
  Top 0.305: DIG5.9 71.46,39.37 71.72,39.37 72.61,40.26 79.21,40.26 80.1,39.37 DIG6.9
  Bottom 0.305: R45.1 83.02,44.07 83.02,43.81 81.88,42.67 81.88,40.64 80.99,39.75 DIG6.9
N$82
  Top 0.305: R47.1 83.53,39.5 83.53,39.24 85.18,37.59 85.18,30.35 83.91,29.08 75.91,29.08 73.75,31.24 DIG6.5
  Bottom 0.305: DIG5.5 63.84,31.75 69.43,31.75 70.32,32.64 71.59,32.64 72.48,31.75 DIG6.5
N$83
  Bottom 0.305: DIG5.2 63.84,39.37 69.43,39.37 70.32,40.26 71.59,40.26 72.48,39.37 DIG6.2 73.75,38.86 74.64,37.97 80.99,37.97 82.89,36.07 R49.1
N$84
  Bottom 0.305: DIG5.3 63.84,36.83 69.43,36.83 70.32,37.72 71.59,37.72 72.48,36.83 DIG6.3 73.75,36.32 74.64,35.43 80.99,35.43 82.77,33.66 R50.1
N$85  (via drill 0.6)
  Top 0.305: v86.07,46.74 86.07,30.35 85.56,29.84 85.56,28.32 PIC2.12
  Bottom 0.305: v86.07,46.74 83.78,49.02 74,49.02 70.19,45.21 R42.2
N$86  (via drill 0.6)
  Top 0.305: v75.02,48.01 73.24,46.23 69.18,46.23 68.16,47.24 65.11,47.24 R41.2 | v87.08,36.45 87.08,28.83 87.59,28.32 PIC2.11
  Bottom 0.305: v75.02,48.01 82.64,48.01 82.89,48.26 83.66,48.26 85.05,46.86 85.05,38.48 v87.08,36.45
N$87
  Top 0.305: DIG5.8 71.46,36.83 71.72,36.83 72.61,37.72 79.21,37.72 80.1,36.83 DIG6.8 80.99,37.21 81.88,38.1 81.88,40.39 83.02,41.53 83.02,41.78 R46.1
N$88
  Bottom 0.305: DIG5.1 63.84,41.91 69.43,41.91 70.32,42.8 71.34,42.8 71.97,42.16 71.97,41.15 72.61,40.51 73.62,40.51 77.18,44.07 77.18,45.59 Q9.C
N$89
  Bottom 0.305: DIG6.1 72.86,42.29 71.46,43.69 62.83,43.69 60.54,45.97 Q10.C
N$90
  Top 0.305: R41.1 70.19,47.75 73.37,47.75 74.64,49.02 76.54,49.02 79.08,46.48 Q9.B
N$91
  Top 0.305: R42.1 63.84,45.21 62.83,46.23 Q10.B
N$92
  Top 0.305: R57.1 60.29,30.99 62.06,30.99 63.97,29.08 68.29,29.08 69.43,27.94 PIC2.18
  Bottom 0.305: CON3.PGC 56.86,13.59 55.72,13.59 52.67,16.64 52.67,28.45 54.19,29.97 58,29.97 59.02,30.99 R57.1
N$93
  Top 0.305: R43.1 90.77,8.89 89.24,8.89 SW+2.P$1_2
  Bottom 0.305: PIC2.2 68.16,20.32 68.67,20.32 69.69,21.34 78.07,21.34 78.96,20.45 78.96,19.18 88.1,10.03 SW+2.P$1_2
N$94
  Top 0.305: R58.1 68.29,17.91 69.81,19.43 PIC2.3
N$95
  Top 0.305: DIG5.7 71.46,34.29 71.72,34.29 72.61,35.18 79.21,35.18 80.1,34.29 DIG6.7 80.99,33.4 82.89,31.5 R51.1
N$96
  Top 0.305: R52.1 80.61,8.89 79.08,8.89 SW-2.P$1_2 78.7,10.16 78.7,11.05 84.04,16.38 84.04,21.72 83.02,22.73 83.02,27.05 PIC2.13
N$97
  Top 0.305: R53.1 70.45,8.89 68.92,8.89 SET2.P$1_2
  Bottom 0.305: PIC2.10 88.1,19.43 92.16,15.37 92.16,9.53 92.67,9.02 92.67,8.26 91.78,7.37 72.73,7.37 71.72,8.38 R53.1
N$98
  Top 0.305: PIC2.9 85.56,20.7 85.56,23.75 89.62,27.81 89.62,45.34 88.61,46.35 R44.2
N$99
  Bottom 0.305: PIC2.8 83.4,20.32 83.91,20.32 91.15,27.56 91.15,41.53 88.61,44.07 R45.2
N$100  (via drill 0.6)
  Top 0.305: v61.05,22.73 69.05,22.73 71.46,20.32 71.97,20.32 PIC2.4
  Bottom 0.305: v61.05,22.73 58.13,22.73 CON3.MCLR
N$101
  Top 0.305: C21.1 61.18,6.1 61.18,9.27 R54.1
  Bottom 0.305: R54.1 60.03,9.4 58.26,9.4 58,9.14 55.33,9.14 CDI2.P$1
N$102
  Top 0.305: R55.2 82.64,12.95 87.21,17.53 LED_AP2.A
N$103  (via drill 0.6)
  Top 0.305: v63.34,24.89 69.43,24.89 71.97,27.43 PIC2.17
  Bottom 0.305: v63.34,24.89 63.34,25.4 60.29,28.45 R59.1
N$104  (via drill 0.6)
  Top 0.305: R56.2 54.83,25.53 54.83,19.05 57.37,16.51 CON3.PGD | v61.3,25.91 65.11,25.91 66.64,27.43 66.89,27.43 PIC2.19
  Bottom 0.305: v61.3,25.91 60.16,24.77 56.35,24.77 55.21,25.91 R56.2
N$105
  Bottom 0.305: R57.2 54.32,31.88 54.32,33.15 52.54,34.92 52.54,38.99 53.56,40.01 LED5.A
N$106
  Top 0.305: R58.2 68.42,12.7 71.97,12.7 Q12.B
  Bottom 0.305: Q11.B 77.05,13.21 73.24,13.21 Q12.B
N$107
  Top 0.305: C21.2 56.1,6.1 56.1,14.99 54.83,16.26 DIRECT2.P$1 | R55.1 81.5,17.4 78.32,17.4 Q11.E 77.05,17.27 73.24,17.27 Q12.E 71.97,17.27 70.95,16.26 67.4,16.26 66.38,17.27 64.61,17.27 R60.1
  Bottom 0.305: C21.2 56.86,5.84 58.51,5.84 62.19,9.53 62.19,15.37 63.72,16.89 R60.1
N$108
  Top 0.305: R59.2 54.32,29.34 54.32,29.84 53.3,30.86 53.3,34.92 LED6.A
N$109
  Bottom 0.305: PIC3.15 78.32,77.43 78.83,77.43 79.84,76.42 83.15,76.42 84.04,77.31 84.04,78.58 88.1,82.64 R70.2
N$110
  Bottom 0.305: PIC3.14 80.86,77.94 81.37,77.94 83.15,79.72 83.66,79.72 87.08,83.15 87.08,83.91 88.1,84.92 R69.2
N$111
  Bottom 0.305: PIC3.7 80.48,70.7 84.92,75.15 86.96,75.15 89.62,77.81 89.62,86.19 88.61,87.21 R68.2
N$112  (via drill 0.6)
  Top 0.305: v82.77,71.59 80.1,71.59 78.83,70.32 78.32,70.32 PIC3.6
  Bottom 0.305: v82.77,71.59 84.29,71.59 90.26,77.56 90.26,87.85 88.61,89.5 R67.2
N$113  (via drill 0.6)
  Top 0.305: v89.88,66.26 89.88,77.18 90.26,77.56 90.26,96.74 88.73,98.26 87.97,98.26 87.08,97.37 87.08,94.07 88.1,93.05 R66.2
  Bottom 0.305: v89.88,66.26 89.88,58.64 89.24,58 87.97,58 87.21,58.76 87.21,59.27 78.07,68.42 77.69,68.42 76.29,69.81 75.78,69.81 PIC3.5
N$114
  Bottom 0.305: PIC3.16 75.78,77.43 76.29,77.43 77.94,75.78 85.05,75.78 86.58,77.31 86.58,78.83 88.1,80.35 R71.2
N$115
  Top 0.305: R68.1 83.53,87.21 83.53,86.96 84.54,85.94 84.54,80.61 83.66,79.72 77.81,79.72 73.75,83.78 DIG8.4
  Bottom 0.305: DIG7.4 63.84,84.29 69.43,84.29 70.32,85.18 71.59,85.18 72.48,84.29 DIG8.4
N$116
  Top 0.305: 79.08,92.8 79.21,92.8 80.1,91.91 DIG8.10 | 79.08,92.8 72.61,92.8 71.72,91.91 71.46,91.91 DIG7.10 | R64.1 82.77,96.61 79.08,92.93 79.08,92.8
N$117
  Top 0.305: DIG7.9 71.46,89.37 71.72,89.37 72.61,90.26 79.21,90.26 80.1,89.37 DIG8.9
  Bottom 0.305: R65.1 83.02,94.07 83.02,93.81 81.88,92.67 81.88,90.64 80.99,89.75 DIG8.9
N$118
  Top 0.305: R67.1 83.53,89.5 83.53,89.24 85.18,87.59 85.18,80.35 83.91,79.08 75.91,79.08 73.75,81.24 DIG8.5
  Bottom 0.305: DIG7.5 63.84,81.75 69.43,81.75 70.32,82.64 71.59,82.64 72.48,81.75 DIG8.5
N$119
  Bottom 0.305: DIG7.2 63.84,89.37 69.43,89.37 70.32,90.26 71.59,90.26 72.48,89.37 DIG8.2 73.75,88.86 74.64,87.97 80.99,87.97 82.89,86.07 R69.1
N$120
  Bottom 0.305: DIG7.3 63.84,86.83 69.43,86.83 70.32,87.72 71.59,87.72 72.48,86.83 DIG8.3 73.75,86.32 74.64,85.43 80.99,85.43 82.77,83.66 R70.1
N$121  (via drill 0.6)
  Top 0.305: v86.07,96.74 86.07,80.35 85.56,79.84 85.56,78.32 PIC3.12
  Bottom 0.305: v86.07,96.74 83.78,99.02 74,99.02 70.19,95.21 R62.2
N$122  (via drill 0.6)
  Top 0.305: v75.02,98.01 73.24,96.23 69.18,96.23 68.16,97.24 65.11,97.24 R61.2 | v87.08,86.45 87.08,78.83 87.59,78.32 PIC3.11
  Bottom 0.305: v75.02,98.01 82.64,98.01 82.89,98.26 83.66,98.26 85.05,96.86 85.05,88.48 v87.08,86.45
N$123
  Top 0.305: DIG7.8 71.46,86.83 71.72,86.83 72.61,87.72 79.21,87.72 80.1,86.83 DIG8.8 80.99,87.21 81.88,88.1 81.88,90.39 83.02,91.53 83.02,91.78 R66.1
N$124
  Bottom 0.305: DIG7.1 63.84,91.91 69.43,91.91 70.32,92.8 71.34,92.8 71.97,92.16 71.97,91.15 72.61,90.51 73.62,90.51 77.18,94.07 77.18,95.59 Q13.C
N$125
  Bottom 0.305: DIG8.1 72.86,92.29 71.46,93.69 62.83,93.69 60.54,95.97 Q14.C
N$126
  Top 0.305: R61.1 70.19,97.75 73.37,97.75 74.64,99.02 76.54,99.02 79.08,96.48 Q13.B
N$127
  Top 0.305: R62.1 63.84,95.21 62.83,96.23 Q14.B
N$128
  Top 0.305: R77.1 60.29,80.99 62.06,80.99 63.97,79.08 68.29,79.08 69.43,77.94 PIC3.18
  Bottom 0.305: CON4.PGC 56.86,63.59 55.72,63.59 52.67,66.64 52.67,78.45 54.19,79.97 58,79.97 59.02,80.99 R77.1
N$129
  Top 0.305: R63.1 90.77,58.89 89.24,58.89 SW+3.P$1_2
  Bottom 0.305: PIC3.2 68.16,70.32 68.67,70.32 69.69,71.34 78.07,71.34 78.96,70.45 78.96,69.18 88.1,60.03 SW+3.P$1_2
N$130
  Top 0.305: R78.1 68.29,67.91 69.81,69.43 PIC3.3
N$131
  Top 0.305: DIG7.7 71.46,84.29 71.72,84.29 72.61,85.18 79.21,85.18 80.1,84.29 DIG8.7 80.99,83.4 82.89,81.5 R71.1
N$132
  Top 0.305: R72.1 80.61,58.89 79.08,58.89 SW-3.P$1_2 78.7,60.16 78.7,61.05 84.04,66.38 84.04,71.72 83.02,72.73 83.02,77.05 PIC3.13
N$133
  Top 0.305: R73.1 70.45,58.89 68.92,58.89 SET3.P$1_2
  Bottom 0.305: PIC3.10 88.1,69.43 92.16,65.37 92.16,59.52 92.67,59.02 92.67,58.26 91.78,57.37 72.73,57.37 71.72,58.38 R73.1
N$134
  Top 0.305: PIC3.9 85.56,70.7 85.56,73.75 89.62,77.81 89.62,95.34 88.61,96.36 R64.2
N$135
  Bottom 0.305: PIC3.8 83.4,70.32 83.91,70.32 91.15,77.56 91.15,91.53 88.61,94.07 R65.2
N$136  (via drill 0.6)
  Top 0.305: v61.05,72.73 69.05,72.73 71.46,70.32 71.97,70.32 PIC3.4
  Bottom 0.305: v61.05,72.73 58.13,72.73 CON4.MCLR
N$137
  Top 0.305: C28.1 61.18,56.1 61.18,59.27 R74.1
  Bottom 0.305: R74.1 60.03,59.4 58.26,59.4 58,59.14 55.33,59.14 CDI3.P$1
N$138
  Top 0.305: R75.2 82.64,62.95 87.21,67.53 LED_AP3.A
N$139  (via drill 0.6)
  Top 0.305: v63.34,74.89 69.43,74.89 71.97,77.43 PIC3.17
  Bottom 0.305: v63.34,74.89 63.34,75.4 60.29,78.45 R79.1
N$140  (via drill 0.6)
  Top 0.305: R76.2 54.83,75.53 54.83,69.05 57.37,66.51 CON4.PGD | v61.3,75.91 65.11,75.91 66.64,77.43 66.89,77.43 PIC3.19
  Bottom 0.305: v61.3,75.91 60.16,74.77 56.35,74.77 55.21,75.91 R76.2
N$141
  Bottom 0.305: R77.2 54.32,81.88 54.32,83.15 52.54,84.92 52.54,88.99 53.56,90 LED7.A
N$142
  Top 0.305: R78.2 68.42,62.7 71.97,62.7 Q16.B
  Bottom 0.305: Q15.B 77.05,63.21 73.24,63.21 Q16.B
N$143
  Top 0.305: C28.2 56.1,56.1 56.1,64.99 54.83,66.26 DIRECT3.P$1 | R75.1 81.5,67.4 78.32,67.4 Q15.E 77.05,67.27 73.24,67.27 Q16.E 71.97,67.27 70.95,66.26 67.4,66.26 66.38,67.27 64.61,67.27 R80.1
  Bottom 0.305: C28.2 56.86,55.84 58.51,55.84 62.19,59.52 62.19,65.37 63.72,66.89 R80.1
N$144
  Top 0.305: R79.2 54.32,79.34 54.32,79.84 53.3,80.86 53.3,84.92 LED8.A
VCC
  Top 0.889: 9.53,21.08 8.38,21.08 CON1.VDD | 9.53,21.08 C5.2 11.81,20.83 12.32,20.32 14.35,20.32 PIC.1 | 7.87,43.31 7.87,41.4 8,41.27 8,27.94 9.27,26.67 R14.1 9.53,25.53 9.53,21.08 | 7.87,43.31 7.87,45.59 Q2.E | Q1.E 24.51,45.97 22.48,43.94 20.83,43.94 20.19,43.31 7.87,43.31 | 26.04,4.7 29.72,4.7 30.61,3.81 R12.2 31.88,3.81 32.38,3.81 33.27,4.7 41.66,4.7 | 26.04,4.7 23.11,4.7 22.23,3.81 21.72,3.81 R11.2 | Q3.C 27.05,14.99 26.04,13.97 26.04,4.7 | 41.66,4.7 41.66,5.59 48.26,12.19 C4.2 C3.2 C2.2 48.26,19.81 46.86,21.21 46.86,22.23 C6.2 | 41.66,4.7 41.66,4.19 R13.2
  Bottom 0.889: IC1.3 47.88,31.24 47.88,24.38 46.99,23.5 C6.2 | PIC.1 15.24,19.43 15.24,18.54 16.13,17.65 16.13,8.89 20.83,4.19 R11.2
  pour Top (isolate 0.61): 0,50 50,50 50,0 0,0
VCC1
  Top 0.889: 9.53,71.08 8.38,71.08 CON2.VDD | 9.53,71.08 C11.2 11.81,70.83 12.32,70.32 14.35,70.32 PIC1.1 | 7.87,93.31 7.87,91.4 8,91.28 8,77.94 9.27,76.67 R36.1 9.53,75.53 9.53,71.08 | 7.87,93.31 7.87,95.59 Q6.E | Q5.E 24.51,95.97 22.48,93.94 20.83,93.94 20.19,93.31 7.87,93.31 | 26.04,54.7 29.72,54.7 30.61,53.81 R32.2 31.88,53.81 32.38,53.81 33.27,54.7 41.66,54.7 | 26.04,54.7 23.11,54.7 22.23,53.81 21.72,53.81 R33.2 | Q7.C 27.05,64.99 26.04,63.97 26.04,54.7 | 41.66,54.7 41.66,55.59 48.26,62.19 C10.2 C9.2 C8.2 48.26,69.81 46.86,71.21 46.86,72.22 C12.2 | 41.66,54.7 41.66,54.19 R23.2
  Bottom 0.889: IC2.3 47.88,81.24 47.88,74.38 46.99,73.5 C12.2 | PIC1.1 15.24,69.43 15.24,68.54 16.13,67.65 16.13,58.89 20.83,54.19 R33.2
  pour Top (isolate 0.61): 0,100 50,100 50,50 0,50
VCC2
  Top 0.889: 59.52,21.08 58.38,21.08 CON3.VDD | 59.52,21.08 C18.2 61.81,20.83 62.32,20.32 64.35,20.32 PIC2.1 | 57.87,43.31 57.87,41.4 58,41.27 58,27.94 59.27,26.67 R56.1 59.52,25.53 59.52,21.08 | 57.87,43.31 57.87,45.59 Q10.E | Q9.E 74.51,45.97 72.48,43.94 70.83,43.94 70.19,43.31 57.87,43.31 | 76.03,4.7 79.72,4.7 80.61,3.81 R52.2 81.88,3.81 82.39,3.81 83.27,4.7 91.66,4.7 | 76.03,4.7 73.11,4.7 72.22,3.81 71.72,3.81 R53.2 | Q11.C 77.05,14.99 76.03,13.97 76.03,4.7 | 91.66,4.7 91.66,5.59 98.26,12.19 C17.2 C16.2 C15.2 98.26,19.81 96.86,21.21 96.86,22.23 C19.2 | 91.66,4.7 91.66,4.19 R43.2
  Bottom 0.889: IC3.3 97.88,31.24 97.88,24.38 96.99,23.5 C19.2 | PIC2.1 65.24,19.43 65.24,18.54 66.13,17.65 66.13,8.89 70.83,4.19 R53.2
  pour Top (isolate 0.61): 50,50 100,50 100,0 50,0
VCC3
  Top 0.889: 59.52,71.08 58.38,71.08 CON4.VDD | 59.52,71.08 C25.2 61.81,70.83 62.32,70.32 64.35,70.32 PIC3.1 | 57.87,93.31 57.87,91.4 58,91.28 58,77.94 59.27,76.67 R76.1 59.52,75.53 59.52,71.08 | 57.87,93.31 57.87,95.59 Q14.E | Q13.E 74.51,95.97 72.48,93.94 70.83,93.94 70.19,93.31 57.87,93.31 | 76.03,54.7 79.72,54.7 80.61,53.81 R72.2 81.88,53.81 82.39,53.81 83.27,54.7 91.66,54.7 | 76.03,54.7 73.11,54.7 72.22,53.81 71.72,53.81 R73.2 | Q15.C 77.05,64.99 76.03,63.97 76.03,54.7 | 91.66,54.7 91.66,55.59 98.26,62.19 C24.2 C23.2 C22.2 98.26,69.81 96.86,71.21 96.86,72.22 C26.2 | 91.66,54.7 91.66,54.19 R63.2
  Bottom 0.889: IC4.3 97.88,81.24 97.88,74.38 96.99,73.5 C26.2 | PIC3.1 65.24,69.43 65.24,68.54 66.13,67.65 66.13,58.89 70.83,54.19 R73.2
  pour Top (isolate 0.61): 50,100 100,100 100,50 50,50

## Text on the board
Dimension: V-CUT | V-CUT | V-CUT | V-CUT
tPlace: - | - | + | + | 12V | 12V | 5V | 5V | - | - | + | + | 12V | 12V | 5V | 5V
_tNames: R9 | Q1 | R9 | Q1 | R1 | R1 | R10 | R2 | R10 | R2 | LED1 | Q2 | C1 | LED1 | Q2 | C1 | R3 | R3 | DIG1 | DIG2 | R4 | DIG1 | DIG2 | R4 | LED2 | R5 | LED2 | R5 | JP1 | JP1 | R6 | R6 | R15 | R7 | R15 | R7 | R16 | R16 | R8 | R8 | R14 | R14 | PIC | PIC | C6 | C6 | DIRECT | C2 | DIRECT | C2 | C5 | R20 | R17 | R19 | C3 | C5 | R20 | R17 | R19 | C3 | LED_AP | LED_AP | Q3 | Q3 | Q4 | Q4 | CDI | R11 | R12 | R13 | C4 | CDI | R11 | R12 | R13 | C4 | R18 | R18 | C7 | C7 | SET | SW- | SW+ | SET | SW- | SW+ | R9 | Q1 | R9 | Q1 | R1 | R1 | R10 | R2 | R10 | R2 | LED1 | Q2 | C1 | LED1 | Q2 | C1 | R3 | R3 | DIG1 | DIG2 | R4 | DIG1 | DIG2 | R4 | LED2 | R5 | LED2 | R5 | JP1 | JP1 | R6 | R6 | R15 | R7 | R15 | R7 | R16 | R16 | R8 | R8 | R14 | R14 | PIC | PIC | C6 | C6 | DIRECT | C2 | DIRECT | C2 | C5 | R20 | R17 | R19 | C3 | C5 | R20 | R17 | R19 | C3 | LED_AP | LED_AP | Q3 | Q3 | Q4 | Q4 | CDI | R11 | R12 | R13 | C4 | CDI | R11 | R12 | R13 | C4 | R18 | R18 | C7 | C7 | SET | SW- | SW+ | SET | SW- | SW+
_bNames: IC1 | IC1 | IC1 | IC1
